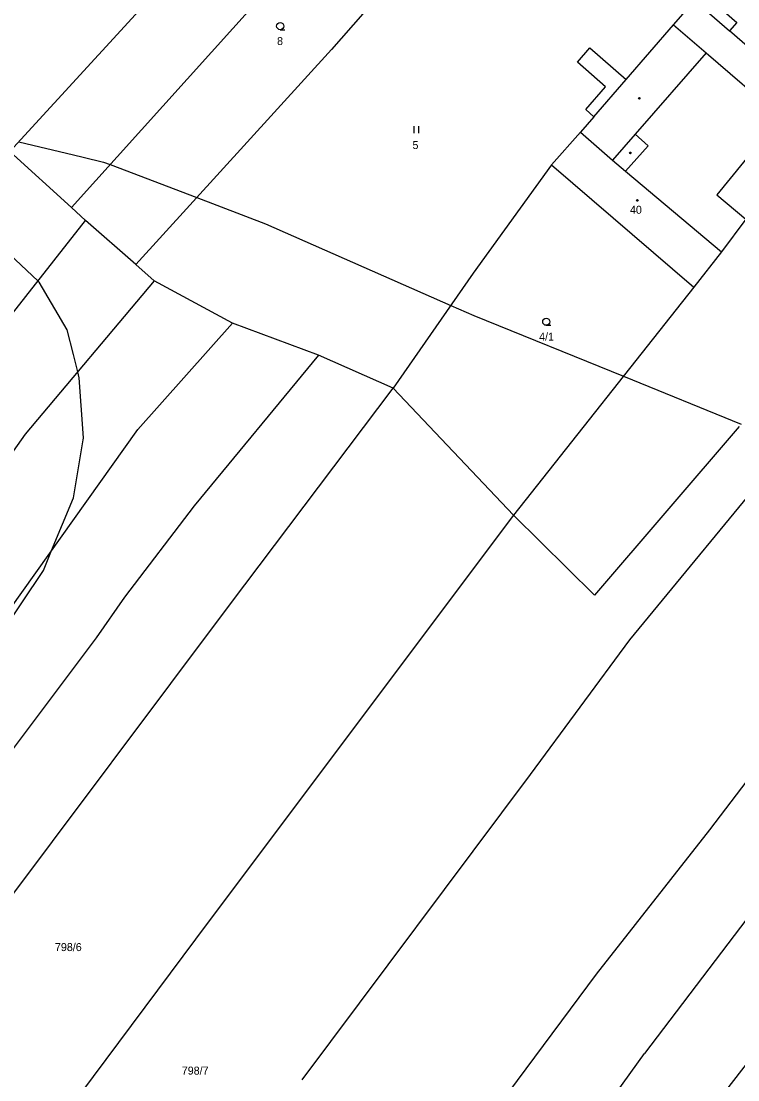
# Model space of a CAD drawing. Extents: x -749173 to -746119, y -1132678 to -1130338.
# Drawn here: x -747979.1 to -747826.9, y -1131323.7 to -1131098.8 of the extents above; entities that cross this region are included whole.
import ezdxf

# ---------------------------------------------------------------- set-up
doc = ezdxf.new("R2010")
doc.units = 0
for name, color, linetype in [('Vrstva 1', 7, 'Continuous'), ('Vrstva 18', 7, 'Continuous'), ('Vrstva 19', 7, 'Continuous'), ('Vrstva 25', 7, 'Continuous'), ('Vrstva 3', 7, 'Continuous'), ('Vrstva 37', 7, 'Continuous'), ('Vrstva 4', 7, 'Continuous'), ('Vrstva 52', 7, 'Continuous'), ('Vrstva 6', 7, 'Continuous')]:
    doc.layers.add(name, color=color, linetype=linetype)

msp = doc.modelspace()

# ---------------------------------------------------------------- linework, layer by layer
at = {"layer": 'Vrstva 1'}
for points in [[(-747916.37, -1131055.44), (-747981.47, -1131126.53)], [(-747904.43, -1131067.33), (-747968.37, -1131138.42)], [(-747886.56, -1131074.48), (-747913.2, -1131104.85)], [(-747840.55, -1131099.64), (-747836.06, -1131094.48)], [(-747832.48, -1131094.48), (-747827.12, -1131099.14)], [(-747850.64, -1131111.24), (-747840.55, -1131099.64)], [(-747827.12, -1131099.14), (-747828.66, -1131100.91)], [(-747813.56, -1131114.04), (-747828.66, -1131100.91)], [(-747913.2, -1131104.85), (-747954.75, -1131150.54)], [(-747860.98, -1131107.54), (-747858.36, -1131104.53)], [(-747858.36, -1131104.53), (-747850.64, -1131111.24)], [(-747854.99, -1131112.75), (-747860.98, -1131107.54)], [(-747859.21, -1131117.61), (-747854.99, -1131112.75)], [(-747857.48, -1131119.12), (-747860.33, -1131122.39)], [(-747857.48, -1131119.12), (-747859.21, -1131117.61)], [(-747866.49, -1131129.32), (-747860.33, -1131122.39)], [(-747968.37, -1131138.42), (-747981.47, -1131126.53)], [(-747866.49, -1131129.32), (-747883.09, -1131152.34)], [(-747866.49, -1131129.32), (-747836.24, -1131155.33)], [(-747968.37, -1131138.42), (-747965.44, -1131141.16)], [(-747954.75, -1131150.54), (-747965.44, -1131141.16)], [(-747825.19, -1131140.88), (-747830.35, -1131147.8)], [(-747830.35, -1131147.8), (-747836.24, -1131155.33)], [(-747950.86, -1131153.99), (-747954.75, -1131150.54)], [(-747883.09, -1131152.34), (-747900.11, -1131176.75)], [(-747934.24, -1131162.98), (-747950.86, -1131153.99)], [(-747836.24, -1131155.33), (-747874.56, -1131203.77)], [(-747915.95, -1131169.75), (-747934.24, -1131162.98)], [(-747900.11, -1131176.75), (-747915.95, -1131169.75)], [(-747874.56, -1131203.77), (-747900.11, -1131176.75)], [(-747826.65, -1131184.92), (-747857.38, -1131220.73)], [(-747857.38, -1131220.73), (-747874.56, -1131203.77)]]:
    msp.add_lwpolyline(points, dxfattribs=at)
at = {"layer": 'Vrstva 25'}
for p, q in [((-747924.09, -1131100.64), (-747923.09, -1131100.64)), ((-747895.68, -1131121.12), (-747895.68, -1131122.62)), ((-747894.68, -1131122.62), (-747894.68, -1131121.12)), ((-747867.6, -1131163.43), (-747866.6, -1131163.43))]:
    msp.add_line(p, q, dxfattribs=at)
for centre, radius in [((-747924.09, -1131099.89), 0.75), ((-747847.82, -1131115.22), 0.175), ((-747849.73, -1131126.81), 0.175), ((-747848.25, -1131136.92), 0.175), ((-747867.6, -1131162.68), 0.75)]:
    msp.add_circle(centre, radius, dxfattribs=at)
at = {"layer": 'Vrstva 3'}
for points in [[(-747866.49, -1131129.32), (-747860.33, -1131122.39)], [(-747860.33, -1131122.39), (-747853.53, -1131128.35)], [(-747866.49, -1131129.32), (-747836.24, -1131155.33)], [(-747853.53, -1131128.35), (-747850.76, -1131130.67)], [(-747850.76, -1131130.67), (-747830.35, -1131147.8)], [(-747830.35, -1131147.8), (-747836.24, -1131155.33)]]:
    msp.add_lwpolyline(points, dxfattribs=at)
at = {"layer": 'Vrstva 37'}
msp.add_circle((-747848.25, -1131136.92), 0.175, dxfattribs=at)
at = {"layer": 'Vrstva 4'}
for points in [[(-747834.02, -1131096.25), (-747828.66, -1131100.91)], [(-747840.55, -1131099.64), (-747833.62, -1131105.57)], [(-747833.62, -1131105.57), (-747848.74, -1131122.86)], [(-747833.62, -1131105.57), (-747817.82, -1131119.12)], [(-747857.48, -1131119.12), (-747850.64, -1131111.24)], [(-747817.82, -1131119.12), (-747831.4, -1131135.72)], [(-747860.33, -1131122.39), (-747853.53, -1131128.35)], [(-747848.74, -1131122.86), (-747853.53, -1131128.35)], [(-747848.74, -1131122.86), (-747845.92, -1131125.34)], [(-747845.92, -1131125.34), (-747850.76, -1131130.67)], [(-747853.53, -1131128.35), (-747850.76, -1131130.67)], [(-747850.76, -1131130.67), (-747830.35, -1131147.8)], [(-747831.4, -1131135.72), (-747825.19, -1131140.88)]]:
    msp.add_lwpolyline(points, dxfattribs=at)
at = {"layer": 'Vrstva 52'}
for points in [[(-747979.58, -1131124.46), (-747967.99, -1131127.23), (-747965.94, -1131127.72), (-747961.62, -1131128.75), (-747960.17, -1131129.3), (-747941.8, -1131136.3)], [(-747941.8, -1131136.3), (-747927.19, -1131141.87), (-747887.87, -1131159.2), (-747882.94, -1131161.37), (-747851.21, -1131174.25), (-747826.21, -1131184.4)], [(-748006.31, -1131263.12), (-747974.37, -1131215.5), (-747972.63, -1131211.29), (-747967.99, -1131200.09), (-747965.94, -1131187.79), (-747965.87, -1131187.37), (-747965.94, -1131186.36), (-747966.75, -1131174.62), (-747967.09, -1131173.28), (-747967.99, -1131169.66), (-747969.31, -1131164.37), (-747975.25, -1131154.25), (-747975.53, -1131153.99), (-747987.56, -1131142.75)]]:
    msp.add_lwpolyline(points, dxfattribs=at)
at = {"layer": 'Vrstva 6'}
for points in [[(-747997.58, -1131182.04), (-747965.44, -1131141.16)], [(-747950.86, -1131153.99), (-747978.25, -1131186.55)], [(-747954.3, -1131185.56), (-747934.24, -1131162.98)], [(-747915.95, -1131169.75), (-747942.37, -1131201.76)], [(-747934.84, -1131222.88), (-747900.11, -1131176.75)], [(-747978.25, -1131186.55), (-747998.39, -1131214.99)], [(-747986.85, -1131231.25), (-747954.3, -1131185.56)], [(-747849.87, -1131230.22), (-747817.77, -1131191.32)], [(-747942.37, -1131201.76), (-747957.17, -1131221.18)], [(-747874.56, -1131203.77), (-747939.35, -1131290.2)], [(-747957.17, -1131221.18), (-747963.16, -1131229.8)], [(-747984.99, -1131289.67), (-747934.84, -1131222.88)], [(-747774.62, -1131223.12), (-747846.71, -1131318.11)], [(-747963.16, -1131229.8), (-747981.45, -1131254.14)], [(-747870.95, -1131258.84), (-747849.87, -1131230.22)], [(-747818.02, -1131250.97), (-747832.91, -1131270.59)], [(-747919.45, -1131323.71), (-747870.95, -1131258.84)], [(-747832.91, -1131270.59), (-747857, -1131301.23)], [(-747939.35, -1131290.2), (-747969.15, -1131330.2)], [(-747857, -1131301.23), (-747888.73, -1131343.94)], [(-747814.92, -1131307.18), (-747846.34, -1131347.72)], [(-747892.39, -1131381.59), (-747846.71, -1131318.11)]]:
    msp.add_lwpolyline(points, dxfattribs=at)

# ---------------------------------------------------------------- texts
at = {"layer": 'Vrstva 18'}
for s, p in [('8', (-747924.76, -1131103.91)), ('5', (-747896, -1131126)), ('4/1', (-747869.11, -1131166.7)), ('798/6', (-747971.92, -1131296.34)), ('798/7', (-747944.99, -1131322.58))]:
    msp.add_text(s, height=1.7, dxfattribs=at).set_placement(p)
at = {"layer": 'Vrstva 19'}
msp.add_text('40', height=1.7, dxfattribs=at).set_placement((-747849.82, -1131139.74))

doc.saveas('drawing.dxf')
